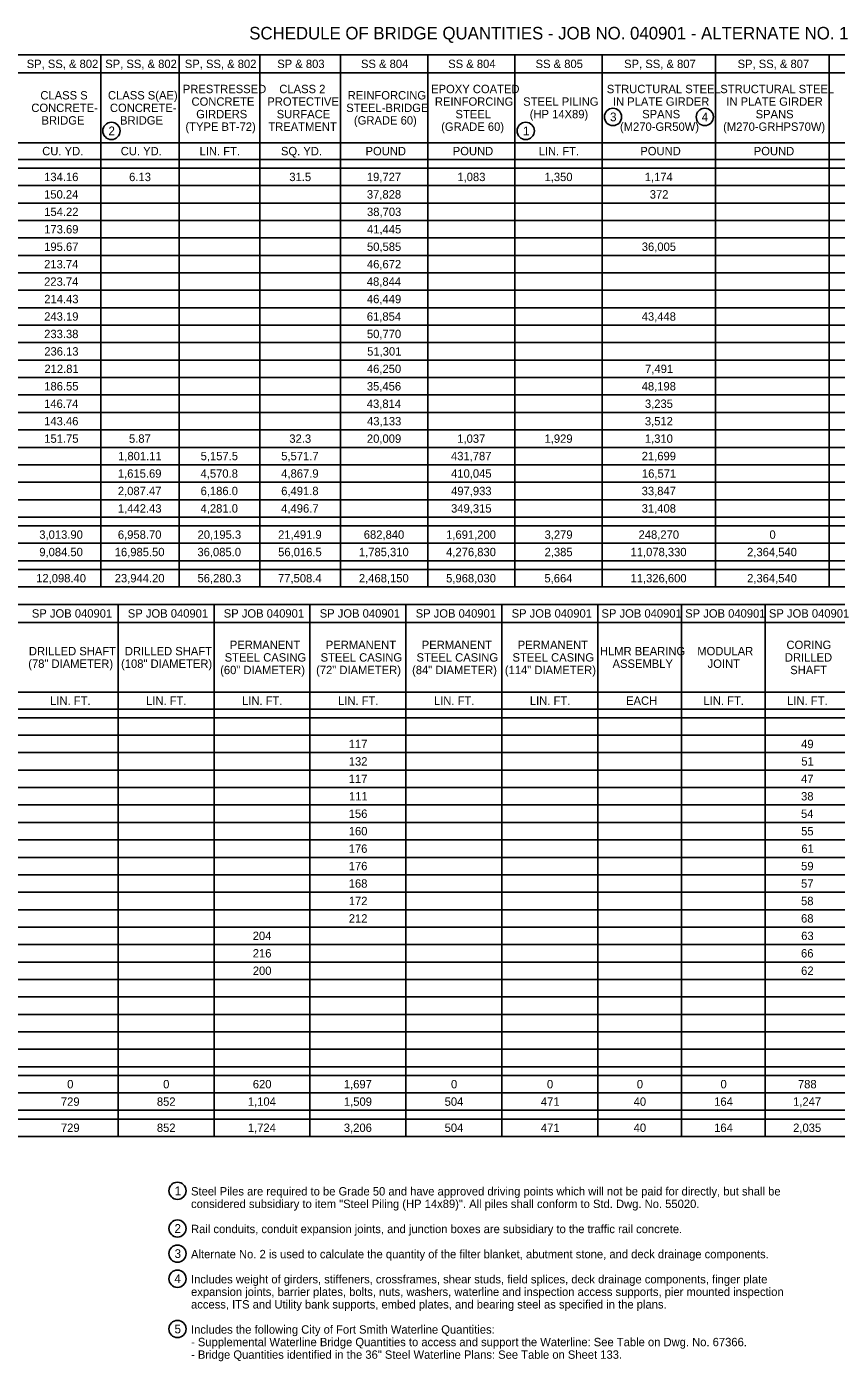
# Model space of a CAD drawing. Extents: x 0.06 to 1.38, y 0.04 to 0.85.
# Drawn here: x 0.423 to 0.907, y 0.057 to 0.854 of the extents above; entities that cross this region are included whole.
import ezdxf

# ---------------------------------------------------------------- set-up
doc = ezdxf.new("R2010")
doc.units = 0
for name, color, linetype in [('R_ROW', 7, 'Continuous'), ('R_Survey Control', 7, 'Continuous'), ('R_Wall', 7, 'Continuous')]:
    doc.layers.add(name, color=color, linetype=linetype)

msp = doc.modelspace()

# ---------------------------------------------------------------- linework, layer by layer
at = {"layer": 'R_Survey Control'}
for p, q in [((0.07508, 0.83695), (1.38207, 0.83695)), ((0.46733, 0.83695), (0.46733, 0.51924)), ((0.51421, 0.83695), (0.51421, 0.51924)), ((0.56236, 0.83695), (0.56236, 0.51924)), ((0.61051, 0.83695), (0.61051, 0.51924)), ((0.66259, 0.83695), (0.66259, 0.51924)), ((0.71468, 0.83695), (0.71468, 0.51924)), ((0.76676, 0.83695), (0.76676, 0.51924)), ((0.83447, 0.83695), (0.83447, 0.51924)), ((0.90222, 0.83695), (0.90222, 0.51924)), ((0.2593, 0.78445), (1.38207, 0.78445)), ((0.07508, 0.77445), (1.38207, 0.77445)), ((0.11154, 0.76924), (1.38207, 0.76924)), ((0.11154, 0.75883), (1.38207, 0.75883)), ((0.11154, 0.74841), (1.38207, 0.74841)), ((0.11154, 0.73799), (1.38207, 0.73799)), ((0.11154, 0.72758), (1.38207, 0.72758)), ((0.11154, 0.71716), (1.38207, 0.71716)), ((0.11154, 0.70674), (1.38207, 0.70674)), ((0.11154, 0.69633), (1.38207, 0.69633)), ((0.11154, 0.68591), (1.38207, 0.68591)), ((0.11154, 0.67549), (1.38207, 0.67549)), ((0.11154, 0.66508), (1.38207, 0.66508)), ((0.11154, 0.65466), (1.38207, 0.65466)), ((0.11154, 0.64424), (1.38207, 0.64424)), ((0.11154, 0.63383), (1.38207, 0.63383)), ((0.11154, 0.62341), (1.38207, 0.62341)), ((0.11154, 0.61299), (1.38207, 0.61299)), ((0.11154, 0.60258), (1.38207, 0.60258)), ((0.11154, 0.59216), (1.38207, 0.59216)), ((0.11154, 0.58174), (1.38207, 0.58174)), ((0.11154, 0.57133), (1.38207, 0.57133)), ((0.11154, 0.56091), (1.38207, 0.56091)), ((0.07508, 0.5557), (1.38207, 0.5557)), ((0.07508, 0.54529), (1.38207, 0.54529)), ((0.07508, 0.53487), (1.38207, 0.53487)), ((0.07508, 0.52966), (1.38207, 0.52966)), ((0.07508, 0.51924), (1.38207, 0.51924)), ((0.07508, 0.50883), (1.30054, 0.50883)), ((0.47769, 0.50883), (0.47769, 0.19112)), ((0.53498, 0.50883), (0.53498, 0.19112)), ((0.59227, 0.50883), (0.59227, 0.19112)), ((0.64957, 0.50883), (0.64957, 0.19112)), ((0.70686, 0.50883), (0.70686, 0.19112)), ((0.76415, 0.50883), (0.76415, 0.19112)), ((0.81414, 0.50883), (0.81414, 0.19112)), ((0.86412, 0.50883), (0.86412, 0.19112)), ((0.2593, 0.45633), (1.30054, 0.45633)), ((0.07508, 0.44633), (1.30054, 0.44633)), ((0.11154, 0.44112), (1.30054, 0.44112)), ((0.11154, 0.4307), (1.30054, 0.4307)), ((0.11154, 0.42029), (1.30054, 0.42029)), ((0.11154, 0.40987), (1.30054, 0.40987)), ((0.11154, 0.39945), (1.30054, 0.39945)), ((0.11154, 0.38904), (1.30054, 0.38904)), ((0.11154, 0.37862), (1.30054, 0.37862)), ((0.11154, 0.3682), (1.30054, 0.3682)), ((0.11154, 0.35779), (1.30054, 0.35779)), ((0.11154, 0.34737), (1.30054, 0.34737)), ((0.11154, 0.33695), (1.30054, 0.33695)), ((0.11154, 0.32654), (1.30054, 0.32654)), ((0.11154, 0.31612), (1.30054, 0.31612)), ((0.11154, 0.3057), (1.30054, 0.3057)), ((0.11154, 0.29529), (1.30054, 0.29529)), ((0.11154, 0.28487), (1.30054, 0.28487)), ((0.11154, 0.27445), (1.30054, 0.27445)), ((0.11154, 0.26404), (1.30054, 0.26404)), ((0.11154, 0.25362), (1.30054, 0.25362)), ((0.11154, 0.2432), (1.30054, 0.2432)), ((0.11154, 0.23279), (1.30054, 0.23279)), ((0.07508, 0.22758), (1.30054, 0.22758)), ((0.07508, 0.21716), (1.30054, 0.21716)), ((0.07508, 0.20674), (1.30054, 0.20674)), ((0.07508, 0.20154), (1.30054, 0.20154)), ((0.07508, 0.19112), (1.30054, 0.19112))]:
    msp.add_line(p, q, dxfattribs=at)
for points in [[(0.2593, 0.82612), (0.30758, 0.82612), (0.41883, 0.82612), (0.46733, 0.82612), (0.509, 0.82612), (0.60403, 0.82612), (0.64048, 0.82612), (0.68476, 0.82612), (0.72903, 0.82612), (0.79673, 0.82612), (0.84248, 0.82612), (0.89457, 0.82612), (0.99353, 0.82612), (1.05082, 0.82612), (1.11332, 0.82612), (1.24092, 0.82612), (1.249, 0.82612), (1.30109, 0.82612), (1.30109, 0.82612), (1.38207, 0.82612)], [(0.2593, 0.49799), (0.30758, 0.49799), (0.36154, 0.49799), (0.40321, 0.49799), (0.44487, 0.49799), (0.49175, 0.49799), (0.52821, 0.49799), (0.58029, 0.49799), (0.64019, 0.49799), (0.7079, 0.49799), (0.75998, 0.49799), (0.81206, 0.49799), (0.85894, 0.49799), (0.86623, 0.49799), (0.92873, 0.49799), (0.99644, 0.49799), (1.06415, 0.49799), (1.11623, 0.49799), (1.16831, 0.49799), (1.30054, 0.49799)]]:
    msp.add_lwpolyline(points, dxfattribs=at)
at = {"layer": 'R_Wall'}
for centre in [(0.77317, 0.79986), (0.828, 0.79986), (0.47374, 0.79152), (0.72109, 0.79152), (0.51317, 0.15868), (0.51317, 0.13618), (0.51317, 0.12118), (0.51317, 0.10618), (0.51317, 0.07618)]:
    msp.add_circle(centre, 0.00515, dxfattribs=at)

# ---------------------------------------------------------------- texts
at = {"layer": 'R_ROW'}
msp.add_text('SCHEDULE OF BRIDGE QUANTITIES - JOB NO. 040901 - ALTERNATE NO. 1', height=0.0075, dxfattribs=at).set_placement((0.55601, 0.84612))
at = {"layer": 'R_Survey Control'}
for s, p in [('SP, SS, & 802', (0.42313, 0.82904)), ('SP, SS, & 802', (0.47003, 0.82904)), ('SP, SS, & 802', (0.51755, 0.82904)), ('SP & 803', (0.57273, 0.82904)), ('SS & 804', (0.62272, 0.82904)), ('SS & 804', (0.6748, 0.82904)), ('SS & 805', (0.72698, 0.82904)), ('SP, SS, & 807', (0.77985, 0.82904)), ('SP, SS, & 807', (0.84758, 0.82904)), ('CLASS S ', (0.4313, 0.81029)), ('CLASS S(AE)', (0.47167, 0.81029)), ('PRESTRESSED', (0.51636, 0.81404)), ('CLASS 2', (0.57397, 0.81404)), ('REINFORCING', (0.61478, 0.81029)), ('EPOXY COATED', (0.66461, 0.81404)), ('STRUCTURAL STEEL', (0.76952, 0.81404)), ('STRUCTURAL STEEL', (0.83725, 0.81404)), ('CONCRETE-', (0.42591, 0.80279)), ('CONCRETE-', (0.47282, 0.80279)), ('CONCRETE', (0.52154, 0.80654)), ('PROTECTIVE', (0.56681, 0.80654)), ('STEEL-BRIDGE', (0.61393, 0.80279)), ('REINFORCING', (0.66686, 0.80654)), ('STEEL PILING', (0.71956, 0.80654)), ('IN PLATE GIRDER', (0.77313, 0.80654)), ('IN PLATE GIRDER', (0.84085, 0.80654)), ('BRIDGE', (0.43198, 0.79529)), ('BRIDGE', (0.47888, 0.79529)), ('GIRDERS', (0.52435, 0.79904)), ('SURFACE', (0.5724, 0.79904)), ('(GRADE 60)', (0.61852, 0.79529)), ('STEEL', (0.67915, 0.79904)), ('(HP 14X89)', (0.72347, 0.79904)), ('SPANS', (0.79062, 0.79904)), ('SPANS', (0.85835, 0.79904)), ('(TYPE BT-72)', (0.51791, 0.79154)), ('TREATMENT', (0.56741, 0.79154)), ('(GRADE 60)', (0.67061, 0.79154)), ('(M270-GR50W)', (0.77736, 0.79154)), ('(M270-GRHPS70W)', (0.83895, 0.79154)), ('CU. YD.', (0.4324, 0.77695)), ('CU. YD.', (0.4793, 0.77695)), ('LIN. FT.', (0.52636, 0.77695)), ('SQ. YD.', (0.57494, 0.77695)), ('POUND', (0.62545, 0.77695)), ('POUND', (0.67753, 0.77695)), ('LIN. FT.', (0.7288, 0.77695)), ('POUND', (0.78951, 0.77695)), ('POUND', (0.85724, 0.77695)), ('134.16', (0.43356, 0.76154)), ('6.13', (0.4843, 0.76154)), ('31.5', (0.57994, 0.76154)), ('19,727', (0.62625, 0.76154)), ('1,083', (0.68028, 0.76154)), ('1,350', (0.73231, 0.76154)), ('1,174', (0.79215, 0.76154)), ('150.24', (0.43353, 0.75112)), ('37,828', (0.62625, 0.75112)), ('372', (0.79514, 0.75112)), ('154.22', (0.4336, 0.7407)), ('38,703', (0.62633, 0.7407)), ('173.69', (0.43359, 0.73029)), ('41,445', (0.62631, 0.73029)), ('195.67', (0.43357, 0.71987)), ('50,585', (0.62631, 0.71987)), ('36,005', (0.79037, 0.71987)), ('213.74', (0.43353, 0.70945)), ('46,672', (0.62628, 0.70945)), ('223.74', (0.43353, 0.69904)), ('48,844', (0.62622, 0.69904)), ('214.43', (0.43364, 0.68862)), ('46,449', (0.62627, 0.68862)), ('243.19', (0.43359, 0.6782)), ('61,854', (0.62622, 0.6782)), ('43,448', (0.79032, 0.6782)), ('233.38', (0.43357, 0.66779)), ('50,770', (0.62627, 0.66779)), ('236.13', (0.43364, 0.65737)), ('51,301', (0.62641, 0.65737)), ('212.81', (0.43372, 0.64695)), ('46,250', (0.62627, 0.64695)), ('7,491', (0.79235, 0.64695)), ('186.55', (0.43362, 0.63654)), ('35,456', (0.62624, 0.63654)), ('48,198', (0.79032, 0.63654)), ('146.74', (0.43353, 0.62612)), ('43,814', (0.62622, 0.62612)), ('3,235', (0.79225, 0.62612)), ('143.46', (0.43356, 0.6157)), ('43,133', (0.62633, 0.6157)), ('3,512', (0.79222, 0.6157)), ('151.75', (0.43362, 0.60529)), ('5.87', (0.48422, 0.60529)), ('32.3', (0.57996, 0.60529)), ('20,009', (0.62627, 0.60529)), ('1,037', (0.68021, 0.60529)), ('1,929', (0.73232, 0.60529)), ('1,310', (0.79221, 0.60529)), ('1,801.11', (0.47771, 0.59487)), ('5,157.5', (0.527, 0.59487)), ('5,571.7', (0.5751, 0.59487)), ('431,787', (0.67646, 0.59487)), ('21,699', (0.79034, 0.59487)), ('1,615.69', (0.47757, 0.58445)), ('4,570.8', (0.52694, 0.58445)), ('4,867.9', (0.57511, 0.58445)), ('410,045', (0.67652, 0.58445)), ('16,571', (0.79047, 0.58445)), ('2,087.47', (0.47756, 0.57404)), ('6,186.0', (0.52696, 0.57404)), ('6,491.8', (0.5751, 0.57404)), ('497,933', (0.67653, 0.57404)), ('33,847', (0.79032, 0.57404)), ('1,442.43', (0.47763, 0.56362)), ('4,281.0', (0.52696, 0.56362)), ('4,496.7', (0.5751, 0.56362)), ('349,315', (0.67652, 0.56362)), ('31,408', (0.79032, 0.56362)), ('3,013.90', (0.43066, 0.54799)), ('6,958.70', (0.47757, 0.54799)), ('20,195.3', (0.52514, 0.54799)), ('21,491.9', (0.57324, 0.54799)), ('682,840', (0.62439, 0.54799)), ('1,691,200', (0.67356, 0.54799)), ('3,279', (0.73232, 0.54799)), ('248,270', (0.78846, 0.54799)), ('0', (0.86661, 0.54799)), ('9,084.50', (0.43066, 0.53758)), ('16,985.50', (0.47569, 0.53758)), ('36,085.0', (0.52508, 0.53758)), ('56,016.5', (0.57327, 0.53758)), ('1,785,310', (0.62148, 0.53758)), ('4,276,830', (0.67356, 0.53758)), ('2,385', (0.73235, 0.53758)), ('11,078,330', (0.78366, 0.53758)), ('2,364,540', (0.85327, 0.53758)), ('12,098.40', (0.42879, 0.52195)), ('23,944.20', (0.47569, 0.52195)), ('56,280.3', (0.52514, 0.52195)), ('77,508.4', (0.57318, 0.52195)), ('2,468,150', (0.62148, 0.52195)), ('5,968,030', (0.67356, 0.52195)), ('5,664', (0.73226, 0.52195)), ('11,326,600', (0.78366, 0.52195)), ('2,364,540', (0.85327, 0.52195)), ('SP JOB 040901', (0.42622, 0.50091)), ('SP JOB 040901', (0.48351, 0.50091)), ('SP JOB 040901', (0.5408, 0.50091)), ('SP JOB 040901', (0.59809, 0.50091)), ('SP JOB 040901', (0.65538, 0.50091)), ('SP JOB 040901', (0.71267, 0.50091)), ('SP JOB 040901', (0.76631, 0.50091)), ('SP JOB 040901', (0.8163, 0.50091)), ('SP JOB 040901', (0.86628, 0.50091)), ('PERMANENT', (0.54443, 0.48216)), ('PERMANENT', (0.60172, 0.48216)), ('PERMANENT', (0.65901, 0.48216)), ('PERMANENT', (0.71631, 0.48216)), ('CORING', (0.87677, 0.48216)), ('DRILLED SHAFT', (0.42444, 0.47841)), ('DRILLED SHAFT', (0.48174, 0.47841)), ('STEEL CASING', (0.54131, 0.47466)), ('STEEL CASING', (0.59861, 0.47466)), ('STEEL CASING', (0.6559, 0.47466)), ('STEEL CASING', (0.71319, 0.47466)), ('HLMR BEARING', (0.76539, 0.47841)), ('MODULAR', (0.8235, 0.47841)), ('DRILLED', (0.87579, 0.47466)), ('(78" DIAMETER)', (0.42406, 0.47091)), ('(108" DIAMETER)', (0.47948, 0.47091)), ('(60" DIAMETER)', (0.53864, 0.46716)), ('(72" DIAMETER)', (0.59594, 0.46716)), ('(84" DIAMETER)', (0.65323, 0.46716)), ('(114" DIAMETER)', (0.70864, 0.46716)), ('ASSEMBLY', (0.77293, 0.47091)), ('JOINT', (0.82968, 0.47091)), ('SHAFT', (0.87901, 0.46716)), ('LIN. FT.', (0.43712, 0.44883)), ('LIN. FT.', (0.49441, 0.44883)), ('LIN. FT.', (0.55171, 0.44883)), ('LIN. FT.', (0.609, 0.44883)), ('LIN. FT.', (0.66629, 0.44883)), ('LIN. FT.', (0.72358, 0.44883)), ('EACH', (0.78102, 0.44883)), ('LIN. FT.', (0.82721, 0.44883)), ('LIN. FT.', (0.87718, 0.44883)), ('117', (0.61541, 0.42299)), ('49', (0.8855, 0.42299)), ('132', (0.61544, 0.41258)), ('51', (0.88564, 0.41258)), ('117', (0.61541, 0.40216)), ('47', (0.88548, 0.40216)), ('111', (0.61557, 0.39174)), ('38', (0.88548, 0.39174)), ('156', (0.6154, 0.38133)), ('54', (0.88545, 0.38133)), ('160', (0.61543, 0.37091)), ('55', (0.88554, 0.37091)), ('176', (0.6154, 0.36049)), ('61', (0.88564, 0.36049)), ('176', (0.6154, 0.35008)), ('59', (0.8855, 0.35008)), ('168', (0.61541, 0.33966)), ('57', (0.88548, 0.33966)), ('172', (0.61544, 0.32924)), ('58', (0.88548, 0.32924)), ('212', (0.61544, 0.31883)), ('68', (0.88548, 0.31883)), ('204', (0.55808, 0.30841)), ('63', (0.88556, 0.30841)), ('216', (0.55811, 0.29799)), ('66', (0.88547, 0.29799)), ('200', (0.55814, 0.28758)), ('62', (0.88551, 0.28758)), ('0', (0.44731, 0.21987)), ('0', (0.5046, 0.21987)), ('620', (0.55814, 0.21987)), ('1,697', (0.6125, 0.21987)), ('0', (0.67647, 0.21987)), ('0', (0.73376, 0.21987)), ('0', (0.7874, 0.21987)), ('0', (0.83739, 0.21987)), ('788', (0.88361, 0.21987)), ('729', (0.44356, 0.20945)), ('852', (0.50086, 0.20945)), ('1,104', (0.55517, 0.20945)), ('1,509', (0.61252, 0.20945)), ('504', (0.67267, 0.20945)), ('471', (0.73015, 0.20945)), ('40', (0.78553, 0.20945)), ('164', (0.83359, 0.20945)), ('1,247', (0.88069, 0.20945)), ('729', (0.44356, 0.19383)), ('852', (0.50086, 0.19383)), ('1,724', (0.55517, 0.19383)), ('3,206', (0.61249, 0.19383)), ('504', (0.67267, 0.19383)), ('471', (0.73015, 0.19383)), ('40', (0.78553, 0.19383)), ('164', (0.83359, 0.19383)), ('2,035', (0.88075, 0.19383))]:
    msp.add_text(s, height=0.005, dxfattribs=at).set_placement(p)
at = {"layer": 'R_Wall'}
for s, height, p in [('3', 0.00521, (0.77142, 0.79725)), ('4', 0.00521, (0.82614, 0.79725)), ('2', 0.00521, (0.47194, 0.78892)), ('1', 0.00521, (0.71942, 0.78892)), ('1', 0.00521, (0.51151, 0.15608)), ('Steel Piles are required to be Grade 50 and have approved driving points which will not be paid for directly, but shall be ', 0.005, (0.52126, 0.1559)), ('considered subsidiary to item "Steel Piling (HP 14x89)". All piles shall conform to Std. Dwg. No. 55020.', 0.005, (0.52126, 0.1484)), ('2', 0.00521, (0.51138, 0.13358)), ('Rail conduits, conduit expansion joints, and junction boxes are subsidiary to the traffic rail concrete.', 0.005, (0.52126, 0.1334)), ('3', 0.00521, (0.51142, 0.11858)), ('Alternate No. 2 is used to calculate the quantity of the filter blanket, abutment stone, and deck drainage components.', 0.005, (0.52126, 0.1184)), ('4', 0.00521, (0.51131, 0.10358)), ('Includes weight of girders, stiffeners, crossframes, shear studs, field splices, deck drainage components, finger plate ', 0.005, (0.52126, 0.1034)), ('expansion joints, barrier plates, bolts, nuts, washers, waterline and inspection access supports, pier mounted inspection ', 0.005, (0.52126, 0.0959)), ('access, ITS and Utility bank supports, embed plates, and bearing steel as specified in the plans.', 0.005, (0.52126, 0.0884)), ('5', 0.00521, (0.51141, 0.07358)), ('Includes the following City of Fort Smith Waterline Quantities:', 0.005, (0.52126, 0.0734)), ('- Supplemental Waterline Bridge Quantities to access and support the Waterline: See Table on Dwg. No. 67366.', 0.005, (0.52126, 0.0659)), ('- Bridge Quantities identified in the 36" Steel Waterline Plans: See Table on Sheet 133.', 0.005, (0.52126, 0.0584))]:
    msp.add_text(s, height=height, dxfattribs=at).set_placement(p)

doc.saveas('drawing.dxf')
